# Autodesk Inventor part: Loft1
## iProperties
Length Units: 11269
Angle Units: 11279
Time Units: 11290
Mass Units: 11283
Angle Display Precision: 1
Created: 1999-06
Part Number: Loft1
Document SubType Name: Modeling
Designer: Administrator
Density: 1 g/cm^3
Control State: 0
Master: False
Checked Out: False
Author: Administrator
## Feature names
1. Extrusion2
2. Hole2
